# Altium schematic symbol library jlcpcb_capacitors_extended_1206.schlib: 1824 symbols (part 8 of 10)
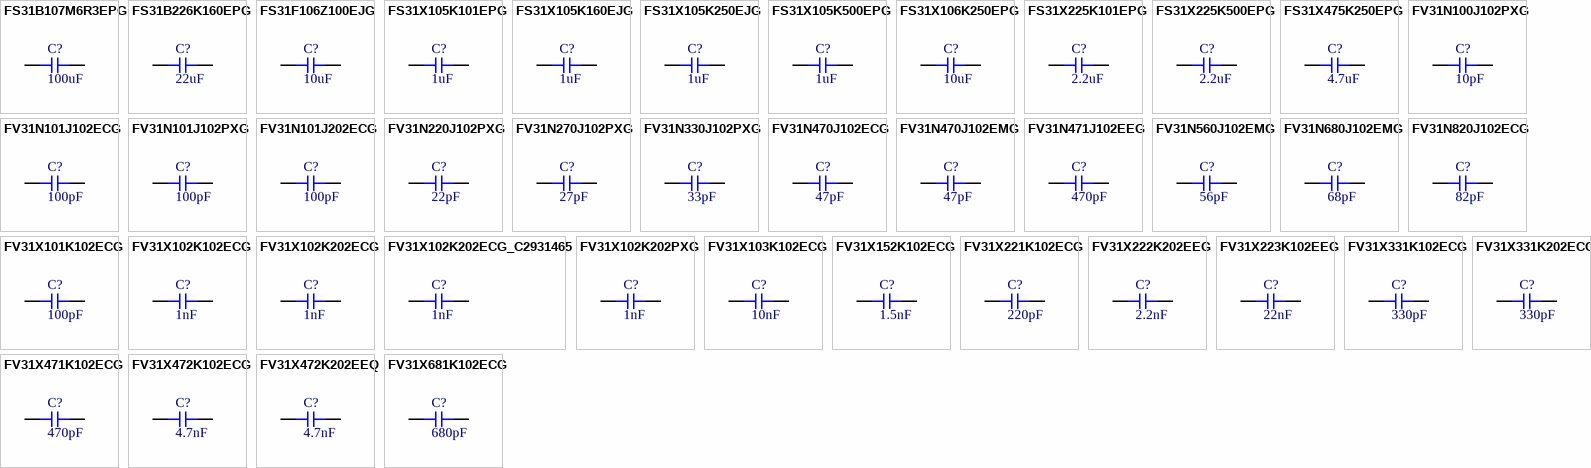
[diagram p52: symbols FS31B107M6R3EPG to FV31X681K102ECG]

## FV31X331K202ECG
designator C?  Capacitance: 330pF  (hidden comment: *)
Capacitor, Ceramic (MLCC), 330pF, ±10%, 2kV, X7R, ±10%, SMD 1206; Manufacturer: PSA(Prosperity Dielectrics); Manufacturer Part Number: FV31X331K202ECG
footprint CAP-1206 (1206 (3216M) Capacitor)
pins: 1, 2

## FV31X471K102ECG
designator C?  Capacitance: 470pF  (hidden comment: *)
Capacitor, Ceramic (MLCC), 470pF, ±10%, 1kV, X7R, ±10%, SMD 1206; Manufacturer: PSA(Prosperity Dielectrics); Manufacturer Part Number: FV31X471K102ECG
footprint CAP-1206 (1206 (3216M) Capacitor)
pins: 1, 2

## FV31X472K102ECG
designator C?  Capacitance: 4.7nF  (hidden comment: *)
Capacitor, Ceramic (MLCC), 4.7nF, ±10%, 1kV, X7R, ±10%, SMD 1206; Manufacturer: PSA(Prosperity Dielectrics); Manufacturer Part Number: FV31X472K102ECG
footprint CAP-1206 (1206 (3216M) Capacitor)
pins: 1, 2

## FV31X472K202EEQ
designator C?  Capacitance: 4.7nF  (hidden comment: *)
Capacitor, Ceramic (MLCC), 4.7nF, ±10%, 2kV, ±10%, SMD 1206; Manufacturer: PSA(Prosperity Dielectrics); Manufacturer Part Number: FV31X472K202EEQ
footprint CAP-1206 (1206 (3216M) Capacitor)
pins: 1, 2

## FV31X681K102ECG
designator C?  Capacitance: 680pF  (hidden comment: *)
Capacitor, Ceramic (MLCC), 680pF, ±10%, 1kV, X7R, ±10%, SMD 1206; Manufacturer: PSA(Prosperity Dielectrics); Manufacturer Part Number: FV31X681K102ECG
footprint CAP-1206 (1206 (3216M) Capacitor)
pins: 1, 2

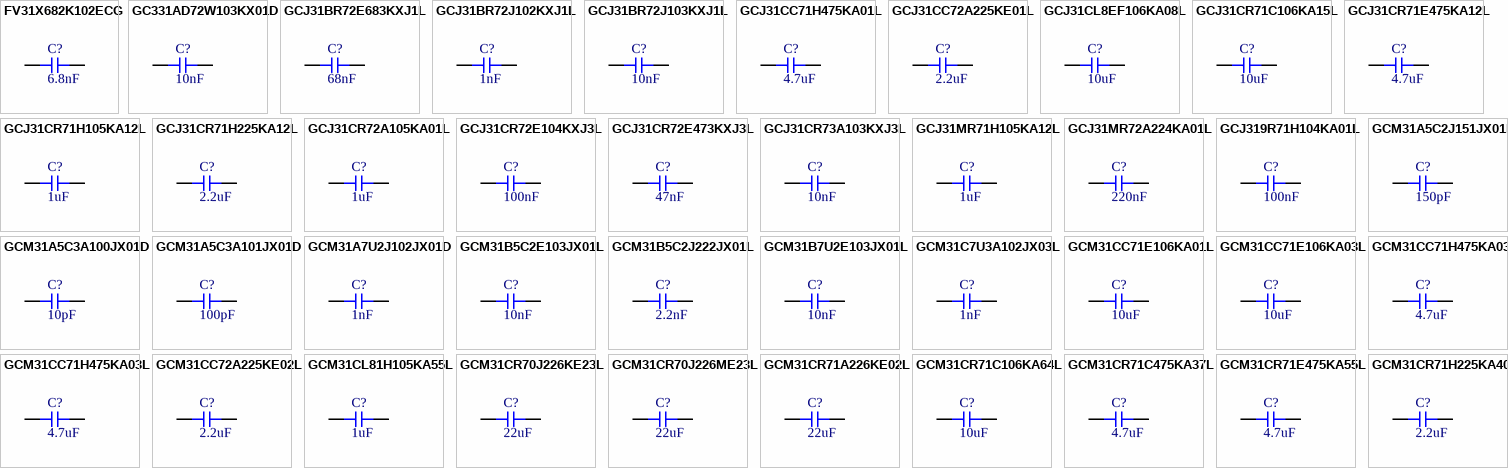
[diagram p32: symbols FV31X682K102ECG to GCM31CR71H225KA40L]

## FV31X682K102ECG
designator C?  Capacitance: 6.8nF  (hidden comment: *)
Capacitor, Ceramic (MLCC), 6.8nF, ±10%, 1kV, X7R, ±10%, SMD 1206; Manufacturer: PSA(Prosperity Dielectrics); Manufacturer Part Number: FV31X682K102ECG
footprint CAP-1206 (1206 (3216M) Capacitor)
pins: 1, 2

## GC331AD72W103KX01D
designator C?  Capacitance: 10nF  (hidden comment: *)
Capacitor, Ceramic (MLCC), 10nF, ±10%, 450V, X7T, ±10%, SMD 1206; Manufacturer: Murata Electronics; Manufacturer Part Number: GC331AD72W103KX01D
footprint CAP-1206 (1206 (3216M) Capacitor)
pins: 1, 2

## GCJ31BR72E683KXJ1L
designator C?  Capacitance: 68nF  (hidden comment: *)
Capacitor, Ceramic (MLCC), 68nF, ±10%, 250V, X7R, ±10%, SMD 1206; Manufacturer: Murata Electronics; Manufacturer Part Number: GCJ31BR72E683KXJ1L
footprint CAP-1206 (1206 (3216M) Capacitor)
pins: 1, 2

## GCJ31BR72J102KXJ1L
designator C?  Capacitance: 1nF  (hidden comment: *)
Capacitor, Ceramic (MLCC), 1nF, ±10%, 630V, X7R, ±10%, SMD 1206; Manufacturer: Murata Electronics; Manufacturer Part Number: GCJ31BR72J102KXJ1L
footprint CAP-1206 (1206 (3216M) Capacitor)
pins: 1, 2

## GCJ31BR72J103KXJ1L
designator C?  Capacitance: 10nF  (hidden comment: *)
Capacitor, Ceramic (MLCC), 10nF, ±10%, 630V, X7R, ±10%, SMD 1206; Manufacturer: Murata Electronics; Manufacturer Part Number: GCJ31BR72J103KXJ1L
footprint CAP-1206 (1206 (3216M) Capacitor)
pins: 1, 2

## GCJ31CC71H475KA01L
designator C?  Capacitance: 4.7uF  (hidden comment: *)
Capacitor, Ceramic (MLCC), 4.7uF, ±10%, 50V, X7S, ±10%, SMD 1206; Manufacturer: Murata Electronics; Manufacturer Part Number: GCJ31CC71H475KA01L
footprint CAP-1206 (1206 (3216M) Capacitor)
pins: 1, 2

## GCJ31CC72A225KE01L
designator C?  Capacitance: 2.2uF  (hidden comment: *)
Capacitor, Ceramic (MLCC), 2.2uF, ±10%, ±10%, SMD 1206; Manufacturer: Murata Electronics; Manufacturer Part Number: GCJ31CC72A225KE01L
footprint CAP-1206 (1206 (3216M) Capacitor)
pins: 1, 2

## GCJ31CL8EF106KA08L
designator C?  Capacitance: 10uF  (hidden comment: *)
Capacitor, Ceramic (MLCC), 10uF, ±10%, X8L, ±10%, SMD 1206; Manufacturer: Murata Electronics; Manufacturer Part Number: GCJ31CL8EF106KA08L
footprint CAP-1206 (1206 (3216M) Capacitor)
pins: 1, 2

## GCJ31CR71C106KA15L
designator C?  Capacitance: 10uF  (hidden comment: *)
Capacitor, Ceramic (MLCC), 10uF, ±10%, ±10%, SMD 1206; Manufacturer: Murata Electronics; Manufacturer Part Number: GCJ31CR71C106KA15L
footprint CAP-1206 (1206 (3216M) Capacitor)
pins: 1, 2

## GCJ31CR71E475KA12L
designator C?  Capacitance: 4.7uF  (hidden comment: *)
Capacitor, Ceramic (MLCC), 4.7uF, ±10%, 25V, X7R, ±10%, SMD 1206; Manufacturer: Murata Electronics; Manufacturer Part Number: GCJ31CR71E475KA12L
footprint CAP-1206 (1206 (3216M) Capacitor)
pins: 1, 2

## GCJ31CR71H105KA12L
designator C?  Capacitance: 1uF  (hidden comment: *)
Capacitor, Ceramic (MLCC), 1uF, ±10%, 50V, X7R, ±10%, SMD 1206; Manufacturer: Murata Electronics; Manufacturer Part Number: GCJ31CR71H105KA12L
footprint CAP-1206 (1206 (3216M) Capacitor)
pins: 1, 2

## GCJ31CR71H225KA12L
designator C?  Capacitance: 2.2uF  (hidden comment: *)
Capacitor, Ceramic (MLCC), 2.2uF, ±10%, 50V, X7R, ±10%, SMD 1206; Manufacturer: Murata Electronics; Manufacturer Part Number: GCJ31CR71H225KA12L
footprint CAP-1206 (1206 (3216M) Capacitor)
pins: 1, 2

## GCJ31CR72A105KA01L
designator C?  Capacitance: 1uF  (hidden comment: *)
Capacitor, Ceramic (MLCC), 1uF, ±10%, 100V, X7R, ±10%, SMD 1206; Manufacturer: Murata Electronics; Manufacturer Part Number: GCJ31CR72A105KA01L
footprint CAP-1206 (1206 (3216M) Capacitor)
pins: 1, 2

## GCJ31CR72E104KXJ3L
designator C?  Capacitance: 100nF  (hidden comment: *)
Capacitor, Ceramic (MLCC), 100nF, ±10%, 250V, X7R, ±10%, SMD 1206; Manufacturer: Murata Electronics; Manufacturer Part Number: GCJ31CR72E104KXJ3L
footprint CAP-1206 (1206 (3216M) Capacitor)
pins: 1, 2

## GCJ31CR72E473KXJ3L
designator C?  Capacitance: 47nF  (hidden comment: *)
Capacitor, Ceramic (MLCC), 47nF, ±10%, 250V, X7R, ±10%, SMD 1206; Manufacturer: Murata Electronics; Manufacturer Part Number: GCJ31CR72E473KXJ3L
footprint CAP-1206 (1206 (3216M) Capacitor)
pins: 1, 2

## GCJ31CR73A103KXJ3L
designator C?  Capacitance: 10nF  (hidden comment: *)
Capacitor, Ceramic (MLCC), 10nF, ±10%, 1kV, X7R, ±10%, SMD 1206; Manufacturer: Murata Electronics; Manufacturer Part Number: GCJ31CR73A103KXJ3L
footprint CAP-1206 (1206 (3216M) Capacitor)
pins: 1, 2

## GCJ31MR71H105KA12L
designator C?  Capacitance: 1uF  (hidden comment: *)
Capacitor, Ceramic (MLCC), 1uF, ±10%, 50V, X7R, ±10%, SMD 1206; Manufacturer: Murata Electronics; Manufacturer Part Number: GCJ31MR71H105KA12L
footprint CAP-1206 (1206 (3216M) Capacitor)
pins: 1, 2

## GCJ31MR72A224KA01L
designator C?  Capacitance: 220nF  (hidden comment: *)
Capacitor, Ceramic (MLCC), 220nF, ±10%, 100V, X7R, ±10%, SMD 1206; Manufacturer: Murata Electronics; Manufacturer Part Number: GCJ31MR72A224KA01L
footprint CAP-1206 (1206 (3216M) Capacitor)
pins: 1, 2

## GCJ319R71H104KA01L
designator C?  Capacitance: 100nF  (hidden comment: *)
Capacitor, Ceramic (MLCC), 100nF, ±10%, 50V, X7R, ±10%, SMD 1206; Manufacturer: Murata Electronics; Manufacturer Part Number: GCJ319R71H104KA01L
footprint CAP-1206 (1206 (3216M) Capacitor)
pins: 1, 2

## GCM31A5C2J151JX01D
designator C?  Capacitance: 150pF  (hidden comment: *)
Capacitor, Ceramic (MLCC), 150pF, ±5%, 630V, C0G, ±5%, SMD 1206; Manufacturer: Murata Electronics; Manufacturer Part Number: GCM31A5C2J151JX01D
footprint CAP-1206 (1206 (3216M) Capacitor)
pins: 1, 2

## GCM31A5C3A100JX01D
designator C?  Capacitance: 10pF  (hidden comment: *)
Capacitor, Ceramic (MLCC), 10pF, ±5%, 1kV, C0G, ±5%, SMD 1206; Manufacturer: Murata Electronics; Manufacturer Part Number: GCM31A5C3A100JX01D
footprint CAP-1206 (1206 (3216M) Capacitor)
pins: 1, 2

## GCM31A5C3A101JX01D
designator C?  Capacitance: 100pF  (hidden comment: *)
Capacitor, Ceramic (MLCC), 100pF, ±5%, 1kV, C0G, ±5%, SMD 1206; Manufacturer: Murata Electronics; Manufacturer Part Number: GCM31A5C3A101JX01D
footprint CAP-1206 (1206 (3216M) Capacitor)
pins: 1, 2

## GCM31A7U2J102JX01D
designator C?  Capacitance: 1nF  (hidden comment: *)
Capacitor, Ceramic (MLCC), 1nF, ±5%, 630V, U2J, ±5%, SMD 1206; Manufacturer: Murata Electronics; Manufacturer Part Number: GCM31A7U2J102JX01D
footprint CAP-1206 (1206 (3216M) Capacitor)
pins: 1, 2

## GCM31B5C2E103JX01L
designator C?  Capacitance: 10nF  (hidden comment: *)
Capacitor, Ceramic (MLCC), 10nF, ±5%, 250V, ±5%, SMD 1206; Manufacturer: Murata Electronics; Manufacturer Part Number: GCM31B5C2E103JX01L
footprint CAP-1206 (1206 (3216M) Capacitor)
pins: 1, 2

## GCM31B5C2J222JX01L
designator C?  Capacitance: 2.2nF  (hidden comment: *)
Capacitor, Ceramic (MLCC), 2.2nF, ±5%, ±5%, SMD 1206; Manufacturer: Murata Electronics; Manufacturer Part Number: GCM31B5C2J222JX01L
footprint CAP-1206 (1206 (3216M) Capacitor)
pins: 1, 2

## GCM31B7U2E103JX01L
designator C?  Capacitance: 10nF  (hidden comment: *)
Capacitor, Ceramic (MLCC), 10nF, ±5%, 250V, U2J, ±5%, SMD 1206; Manufacturer: Murata Electronics; Manufacturer Part Number: GCM31B7U2E103JX01L
footprint CAP-1206 (1206 (3216M) Capacitor)
pins: 1, 2

## GCM31C7U3A102JX03L
designator C?  Capacitance: 1nF  (hidden comment: *)
Capacitor, Ceramic (MLCC), 1nF, ±5%, 1kV, U2J, ±5%, SMD 1206; Manufacturer: Murata Electronics; Manufacturer Part Number: GCM31C7U3A102JX03L
footprint CAP-1206 (1206 (3216M) Capacitor)
pins: 1, 2

## GCM31CC71E106KA01L
designator C?  Capacitance: 10uF  (hidden comment: *)
Capacitor, Ceramic (MLCC), 10uF, ±10%, 25V, X7S, ±10%, SMD 1206; Manufacturer: Murata Electronics; Manufacturer Part Number: GCM31CC71E106KA01L
footprint CAP-1206 (1206 (3216M) Capacitor)
pins: 1, 2

## GCM31CC71E106KA03L
designator C?  Capacitance: 10uF  (hidden comment: *)
Capacitor, Ceramic (MLCC), 10uF, ±10%, 25V, X7S, ±10%, SMD 1206; Manufacturer: Murata Electronics; Manufacturer Part Number: GCM31CC71E106KA03L
footprint CAP-1206 (1206 (3216M) Capacitor)
pins: 1, 2

## GCM31CC71H475KA03K
designator C?  Capacitance: 4.7uF  (hidden comment: *)
Capacitor, Ceramic (MLCC), 4.7uF, ±10%, 50V, ±10%, SMD 1206; Manufacturer: Murata Electronics; Manufacturer Part Number: GCM31CC71H475KA03K
footprint CAP-1206 (1206 (3216M) Capacitor)
pins: 1, 2

## GCM31CC71H475KA03L
designator C?  Capacitance: 4.7uF  (hidden comment: *)
Capacitor, Ceramic (MLCC), 4.7uF, ±10%, 50V, X7S, ±10%, SMD 1206; Manufacturer: Murata Electronics; Manufacturer Part Number: GCM31CC71H475KA03L
footprint CAP-1206 (1206 (3216M) Capacitor)
pins: 1, 2

## GCM31CC72A225KE02L
designator C?  Capacitance: 2.2uF  (hidden comment: *)
Capacitor, Ceramic (MLCC), 2.2uF, ±10%, 100V, X7S, ±10%, SMD 1206; Manufacturer: Murata Electronics; Manufacturer Part Number: GCM31CC72A225KE02L
footprint CAP-1206 (1206 (3216M) Capacitor)
pins: 1, 2

## GCM31CL81H105KA55L
designator C?  Capacitance: 1uF  (hidden comment: *)
Capacitor, Ceramic (MLCC), 1uF, ±10%, 50V, X8L, ±10%, SMD 1206; Manufacturer: Murata Electronics; Manufacturer Part Number: GCM31CL81H105KA55L
footprint CAP-1206 (1206 (3216M) Capacitor)
pins: 1, 2

## GCM31CR70J226KE23L
designator C?  Capacitance: 22uF  (hidden comment: *)
Capacitor, Ceramic (MLCC), 22uF, ±10%, 6.3V, X7R, ±10%, SMD 1206; Manufacturer: Murata Electronics; Manufacturer Part Number: GCM31CR70J226KE23L
footprint CAP-1206 (1206 (3216M) Capacitor)
pins: 1, 2

## GCM31CR70J226ME23L
designator C?  Capacitance: 22uF  (hidden comment: *)
Capacitor, Ceramic (MLCC), 22uF, ±20%, 6.3V, X7R, ±20%, SMD 1206; Manufacturer: Murata Electronics; Manufacturer Part Number: GCM31CR70J226ME23L
footprint CAP-1206 (1206 (3216M) Capacitor)
pins: 1, 2

## GCM31CR71A226KE02L
designator C?  Capacitance: 22uF  (hidden comment: *)
Capacitor, Ceramic (MLCC), 22uF, ±10%, 10V, X7R, ±10%, SMD 1206; Manufacturer: Murata Electronics; Manufacturer Part Number: GCM31CR71A226KE02L
footprint CAP-1206 (1206 (3216M) Capacitor)
pins: 1, 2

## GCM31CR71C106KA64L
designator C?  Capacitance: 10uF  (hidden comment: *)
Capacitor, Ceramic (MLCC), 10uF, ±10%, 16V, X7R, ±10%, SMD 1206; Manufacturer: Murata Electronics; Manufacturer Part Number: GCM31CR71C106KA64L
footprint CAP-1206 (1206 (3216M) Capacitor)
pins: 1, 2

## GCM31CR71C475KA37L
designator C?  Capacitance: 4.7uF  (hidden comment: *)
Capacitor, Ceramic (MLCC), 4.7uF, ±10%, 16V, X7R, ±10%, SMD 1206; Manufacturer: Murata Electronics; Manufacturer Part Number: GCM31CR71C475KA37L
footprint CAP-1206 (1206 (3216M) Capacitor)
pins: 1, 2

## GCM31CR71E475KA55L
designator C?  Capacitance: 4.7uF  (hidden comment: *)
Capacitor, Ceramic (MLCC), 4.7uF, ±10%, 25V, X7R, ±10%, SMD 1206; Manufacturer: Murata Electronics; Manufacturer Part Number: GCM31CR71E475KA55L
footprint CAP-1206 (1206 (3216M) Capacitor)
pins: 1, 2

## GCM31CR71H225KA40L
designator C?  Capacitance: 2.2uF  (hidden comment: *)
Capacitor, Ceramic (MLCC), 2.2uF, ±10%, 50V, X7R, ±10%, SMD 1206; Manufacturer: Murata Electronics; Manufacturer Part Number: GCM31CR71H225KA40L
footprint CAP-1206 (1206 (3216M) Capacitor)
pins: 1, 2

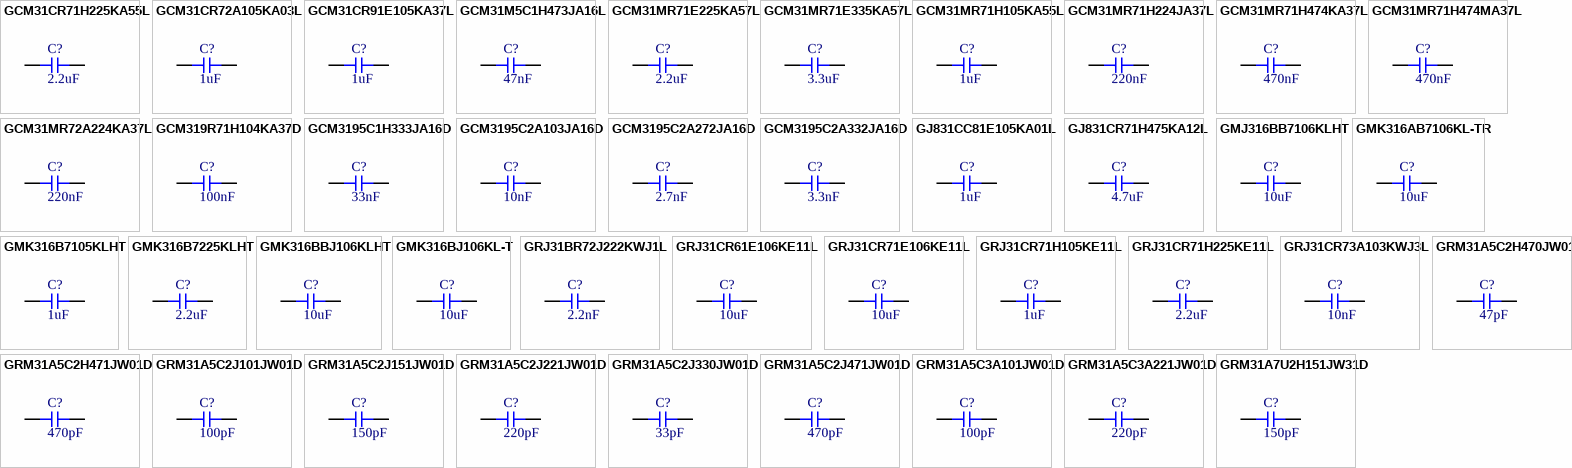
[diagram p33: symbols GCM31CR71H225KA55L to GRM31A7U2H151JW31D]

## GCM31CR71H225KA55L
designator C?  Capacitance: 2.2uF  (hidden comment: *)
Capacitor, Ceramic (MLCC), 2.2uF, ±10%, 50V, X7R, ±10%, SMD 1206; Manufacturer: Murata Electronics; Manufacturer Part Number: GCM31CR71H225KA55L
footprint CAP-1206 (1206 (3216M) Capacitor)
pins: 1, 2

## GCM31CR72A105KA03L
designator C?  Capacitance: 1uF  (hidden comment: *)
Capacitor, Ceramic (MLCC), 1uF, ±10%, 100V, X7R, ±10%, SMD 1206; Manufacturer: Murata Electronics; Manufacturer Part Number: GCM31CR72A105KA03L
footprint CAP-1206 (1206 (3216M) Capacitor)
pins: 1, 2

## GCM31CR91E105KA37L
designator C?  Capacitance: 1uF  (hidden comment: *)
Capacitor, Ceramic (MLCC), 1uF, ±10%, 25V, X8R, ±10%, SMD 1206; Manufacturer: Murata Electronics; Manufacturer Part Number: GCM31CR91E105KA37L
footprint CAP-1206 (1206 (3216M) Capacitor)
pins: 1, 2

## GCM31M5C1H473JA16L
designator C?  Capacitance: 47nF  (hidden comment: *)
Capacitor, Ceramic (MLCC), 47nF, ±5%, ±5%, SMD 1206; Manufacturer: Murata Electronics; Manufacturer Part Number: GCM31M5C1H473JA16L
footprint CAP-1206 (1206 (3216M) Capacitor)
pins: 1, 2

## GCM31MR71E225KA57L
designator C?  Capacitance: 2.2uF  (hidden comment: *)
Capacitor, Ceramic (MLCC), 2.2uF, ±10%, 25V, X7R, ±10%, SMD 1206; Manufacturer: Murata Electronics; Manufacturer Part Number: GCM31MR71E225KA57L
footprint CAP-1206 (1206 (3216M) Capacitor)
pins: 1, 2

## GCM31MR71E335KA57L
designator C?  Capacitance: 3.3uF  (hidden comment: *)
Capacitor, Ceramic (MLCC), 3.3uF, ±10%, 25V, X7R, ±10%, SMD 1206; Manufacturer: Murata Electronics; Manufacturer Part Number: GCM31MR71E335KA57L
footprint CAP-1206 (1206 (3216M) Capacitor)
pins: 1, 2

## GCM31MR71H105KA55L
designator C?  Capacitance: 1uF  (hidden comment: *)
Capacitor, Ceramic (MLCC), 1uF, ±10%, 50V, X7R, ±10%, SMD 1206; Manufacturer: Murata Electronics; Manufacturer Part Number: GCM31MR71H105KA55L
footprint CAP-1206 (1206 (3216M) Capacitor)
pins: 1, 2

## GCM31MR71H224JA37L
designator C?  Capacitance: 220nF  (hidden comment: *)
Capacitor, Ceramic (MLCC), 220nF, ±5%, 50V, X7R, ±5%, SMD 1206; Manufacturer: Murata Electronics; Manufacturer Part Number: GCM31MR71H224JA37L
footprint CAP-1206 (1206 (3216M) Capacitor)
pins: 1, 2

## GCM31MR71H474KA37L
designator C?  Capacitance: 470nF  (hidden comment: *)
Capacitor, Ceramic (MLCC), 470nF, ±10%, 50V, X7R, ±10%, SMD 1206; Manufacturer: Murata Electronics; Manufacturer Part Number: GCM31MR71H474KA37L
footprint CAP-1206 (1206 (3216M) Capacitor)
pins: 1, 2

## GCM31MR71H474MA37L
designator C?  Capacitance: 470nF  (hidden comment: *)
Capacitor, Ceramic (MLCC), 470nF, ±20%, 50V, X7R, ±20%, SMD 1206; Manufacturer: Murata Electronics; Manufacturer Part Number: GCM31MR71H474MA37L
footprint CAP-1206 (1206 (3216M) Capacitor)
pins: 1, 2

## GCM31MR72A224KA37L
designator C?  Capacitance: 220nF  (hidden comment: *)
Capacitor, Ceramic (MLCC), 220nF, ±10%, 100V, X7R, ±10%, SMD 1206; Manufacturer: Murata Electronics; Manufacturer Part Number: GCM31MR72A224KA37L
footprint CAP-1206 (1206 (3216M) Capacitor)
pins: 1, 2

## GCM319R71H104KA37D
designator C?  Capacitance: 100nF  (hidden comment: *)
Capacitor, Ceramic (MLCC), 100nF, ±10%, 50V, X7R, ±10%, SMD 1206; Manufacturer: Murata Electronics; Manufacturer Part Number: GCM319R71H104KA37D
footprint CAP-1206 (1206 (3216M) Capacitor)
pins: 1, 2

## GCM3195C1H333JA16D
designator C?  Capacitance: 33nF  (hidden comment: *)
Capacitor, Ceramic (MLCC), 33nF, ±5%, 50V, C0G, ±5%, SMD 1206; Manufacturer: Murata Electronics; Manufacturer Part Number: GCM3195C1H333JA16D
footprint CAP-1206 (1206 (3216M) Capacitor)
pins: 1, 2

## GCM3195C2A103JA16D
designator C?  Capacitance: 10nF  (hidden comment: *)
Capacitor, Ceramic (MLCC), 10nF, ±5%, 100V, C0G, ±5%, SMD 1206; Manufacturer: Murata Electronics; Manufacturer Part Number: GCM3195C2A103JA16D
footprint CAP-1206 (1206 (3216M) Capacitor)
pins: 1, 2

## GCM3195C2A272JA16D
designator C?  Capacitance: 2.7nF  (hidden comment: *)
Capacitor, Ceramic (MLCC), 2.7nF, ±5%, 100V, C0G, ±5%, SMD 1206; Manufacturer: Murata Electronics; Manufacturer Part Number: GCM3195C2A272JA16D
footprint CAP-1206 (1206 (3216M) Capacitor)
pins: 1, 2

## GCM3195C2A332JA16D
designator C?  Capacitance: 3.3nF  (hidden comment: *)
Capacitor, Ceramic (MLCC), 3.3nF, ±5%, 100V, C0G, ±5%, SMD 1206; Manufacturer: Murata Electronics; Manufacturer Part Number: GCM3195C2A332JA16D
footprint CAP-1206 (1206 (3216M) Capacitor)
pins: 1, 2

## GJ831CC81E105KA01L
designator C?  Capacitance: 1uF  (hidden comment: *)
Capacitor, Ceramic (MLCC), 1uF, ±10%, 25V, X6S, ±10%, SMD 1206; Manufacturer: Murata Electronics; Manufacturer Part Number: GJ831CC81E105KA01L
footprint CAP-1206 (1206 (3216M) Capacitor)
pins: 1, 2

## GJ831CR71H475KA12L
designator C?  Capacitance: 4.7uF  (hidden comment: *)
Capacitor, Ceramic (MLCC), 4.7uF, ±10%, 50V, X7R, ±10%, SMD 1206; Manufacturer: Murata Electronics; Manufacturer Part Number: GJ831CR71H475KA12L
footprint CAP-1206 (1206 (3216M) Capacitor)
pins: 1, 2

## GMJ316BB7106KLHT
designator C?  Capacitance: 10uF  (hidden comment: *)
Capacitor, Ceramic (MLCC), 10uF, ±10%, 35V, X7R, ±10%, SMD 1206; Manufacturer: Taiyo Yuden; Manufacturer Part Number: GMJ316BB7106KLHT
footprint CAP-1206 (1206 (3216M) Capacitor)
pins: 1, 2

## GMK316AB7106KL-TR
designator C?  Capacitance: 10uF  (hidden comment: *)
Capacitor, Ceramic (MLCC), 10uF, ±10%, 35V, X7R, ±10%, SMD 1206; Manufacturer: Taiyo Yuden; Manufacturer Part Number: GMK316AB7106KL-TR
footprint CAP-1206 (1206 (3216M) Capacitor)
pins: 1, 2

## GMK316B7105KLHT
designator C?  Capacitance: 1uF  (hidden comment: *)
Capacitor, Ceramic (MLCC), 1uF, ±10%, 35V, X7R, ±10%, SMD 1206; Manufacturer: Taiyo Yuden; Manufacturer Part Number: GMK316B7105KLHT
footprint CAP-1206 (1206 (3216M) Capacitor)
pins: 1, 2

## GMK316B7225KLHT
designator C?  Capacitance: 2.2uF  (hidden comment: *)
Capacitor, Ceramic (MLCC), 2.2uF, ±10%, 35V, X7R, ±10%, SMD 1206; Manufacturer: Taiyo Yuden; Manufacturer Part Number: GMK316B7225KLHT
footprint CAP-1206 (1206 (3216M) Capacitor)
pins: 1, 2

## GMK316BBJ106KLHT
designator C?  Capacitance: 10uF  (hidden comment: *)
Capacitor, Ceramic (MLCC), 10uF, ±10%, 35V, X5R, ±10%, SMD 1206; Manufacturer: Taiyo Yuden; Manufacturer Part Number: GMK316BBJ106KLHT
footprint CAP-1206 (1206 (3216M) Capacitor)
pins: 1, 2

## GMK316BJ106KL-T
designator C?  Capacitance: 10uF  (hidden comment: *)
Capacitor, Ceramic (MLCC), 10uF, ±10%, 35V, X5R, ±10%, SMD 1206; Manufacturer: Taiyo Yuden; Manufacturer Part Number: GMK316BJ106KL-T
footprint CAP-1206 (1206 (3216M) Capacitor)
pins: 1, 2

## GRJ31BR72J222KWJ1L
designator C?  Capacitance: 2.2nF  (hidden comment: *)
Capacitor, Ceramic (MLCC), 2.2nF, ±10%, 630V, X7R, ±10%, SMD 1206; Manufacturer: Murata Electronics; Manufacturer Part Number: GRJ31BR72J222KWJ1L
footprint CAP-1206 (1206 (3216M) Capacitor)
pins: 1, 2

## GRJ31CR61E106KE11L
designator C?  Capacitance: 10uF  (hidden comment: *)
Capacitor, Ceramic (MLCC), 10uF, ±10%, 25V, X5R, ±10%, SMD 1206; Manufacturer: Murata Electronics; Manufacturer Part Number: GRJ31CR61E106KE11L
footprint CAP-1206 (1206 (3216M) Capacitor)
pins: 1, 2

## GRJ31CR71E106KE11L
designator C?  Capacitance: 10uF  (hidden comment: *)
Capacitor, Ceramic (MLCC), 10uF, ±10%, 25V, X7R, ±10%, SMD 1206; Manufacturer: Murata Electronics; Manufacturer Part Number: GRJ31CR71E106KE11L
footprint CAP-1206 (1206 (3216M) Capacitor)
pins: 1, 2

## GRJ31CR71H105KE11L
designator C?  Capacitance: 1uF  (hidden comment: *)
Capacitor, Ceramic (MLCC), 1uF, ±10%, 50V, X7R, ±10%, SMD 1206; Manufacturer: Murata Electronics; Manufacturer Part Number: GRJ31CR71H105KE11L
footprint CAP-1206 (1206 (3216M) Capacitor)
pins: 1, 2

## GRJ31CR71H225KE11L
designator C?  Capacitance: 2.2uF  (hidden comment: *)
Capacitor, Ceramic (MLCC), 2.2uF, ±10%, 50V, X7R, ±10%, SMD 1206; Manufacturer: Murata Electronics; Manufacturer Part Number: GRJ31CR71H225KE11L
footprint CAP-1206 (1206 (3216M) Capacitor)
pins: 1, 2

## GRJ31CR73A103KWJ3L
designator C?  Capacitance: 10nF  (hidden comment: *)
Capacitor, Ceramic (MLCC), 10nF, ±10%, 1kV, X7R, ±10%, SMD 1206; Manufacturer: Murata Electronics; Manufacturer Part Number: GRJ31CR73A103KWJ3L
footprint CAP-1206 (1206 (3216M) Capacitor)
pins: 1, 2

## GRM31A5C2H470JW01D
designator C?  Capacitance: 47pF  (hidden comment: *)
Capacitor, Ceramic (MLCC), 47pF, ±5%, 500V, C0G, ±5%, SMD 1206; Manufacturer: Murata Electronics; Manufacturer Part Number: GRM31A5C2H470JW01D
footprint CAP-1206 (1206 (3216M) Capacitor)
pins: 1, 2

## GRM31A5C2H471JW01D
designator C?  Capacitance: 470pF  (hidden comment: *)
Capacitor, Ceramic (MLCC), 470pF, ±5%, 500V, C0G, ±5%, SMD 1206; Manufacturer: Murata Electronics; Manufacturer Part Number: GRM31A5C2H471JW01D
footprint CAP-1206 (1206 (3216M) Capacitor)
pins: 1, 2

## GRM31A5C2J101JW01D
designator C?  Capacitance: 100pF  (hidden comment: *)
Capacitor, Ceramic (MLCC), 100pF, ±5%, 630V, C0G, ±5%, SMD 1206; Manufacturer: Murata Electronics; Manufacturer Part Number: GRM31A5C2J101JW01D
footprint CAP-1206 (1206 (3216M) Capacitor)
pins: 1, 2

## GRM31A5C2J151JW01D
designator C?  Capacitance: 150pF  (hidden comment: *)
Capacitor, Ceramic (MLCC), 150pF, ±5%, 630V, C0G, ±5%, SMD 1206; Manufacturer: Murata Electronics; Manufacturer Part Number: GRM31A5C2J151JW01D
footprint CAP-1206 (1206 (3216M) Capacitor)
pins: 1, 2

## GRM31A5C2J221JW01D
designator C?  Capacitance: 220pF  (hidden comment: *)
Capacitor, Ceramic (MLCC), 220pF, ±5%, 630V, C0G, ±5%, SMD 1206; Manufacturer: Murata Electronics; Manufacturer Part Number: GRM31A5C2J221JW01D
footprint CAP-1206 (1206 (3216M) Capacitor)
pins: 1, 2

## GRM31A5C2J330JW01D
designator C?  Capacitance: 33pF  (hidden comment: *)
Capacitor, Ceramic (MLCC), 33pF, ±5%, 630V, C0G, ±5%, SMD 1206; Manufacturer: Murata Electronics; Manufacturer Part Number: GRM31A5C2J330JW01D
footprint CAP-1206 (1206 (3216M) Capacitor)
pins: 1, 2

## GRM31A5C2J471JW01D
designator C?  Capacitance: 470pF  (hidden comment: *)
Capacitor, Ceramic (MLCC), 470pF, ±5%, 630V, C0G, ±5%, SMD 1206; Manufacturer: Murata Electronics; Manufacturer Part Number: GRM31A5C2J471JW01D
footprint CAP-1206 (1206 (3216M) Capacitor)
pins: 1, 2

## GRM31A5C3A101JW01D
designator C?  Capacitance: 100pF  (hidden comment: *)
Capacitor, Ceramic (MLCC), 100pF, ±5%, 1kV, C0G, ±5%, SMD 1206; Manufacturer: Murata Electronics; Manufacturer Part Number: GRM31A5C3A101JW01D
footprint CAP-1206 (1206 (3216M) Capacitor)
pins: 1, 2

## GRM31A5C3A221JW01D
designator C?  Capacitance: 220pF  (hidden comment: *)
Capacitor, Ceramic (MLCC), 220pF, ±5%, 1kV, C0G, ±5%, SMD 1206; Manufacturer: Murata Electronics; Manufacturer Part Number: GRM31A5C3A221JW01D
footprint CAP-1206 (1206 (3216M) Capacitor)
pins: 1, 2

## GRM31A7U2H151JW31D
designator C?  Capacitance: 150pF  (hidden comment: *)
Capacitor, Ceramic (MLCC), 150pF, ±5%, 500V, U2J, ±5%, SMD 1206; Manufacturer: Murata Electronics; Manufacturer Part Number: GRM31A7U2H151JW31D
footprint CAP-1206 (1206 (3216M) Capacitor)
pins: 1, 2

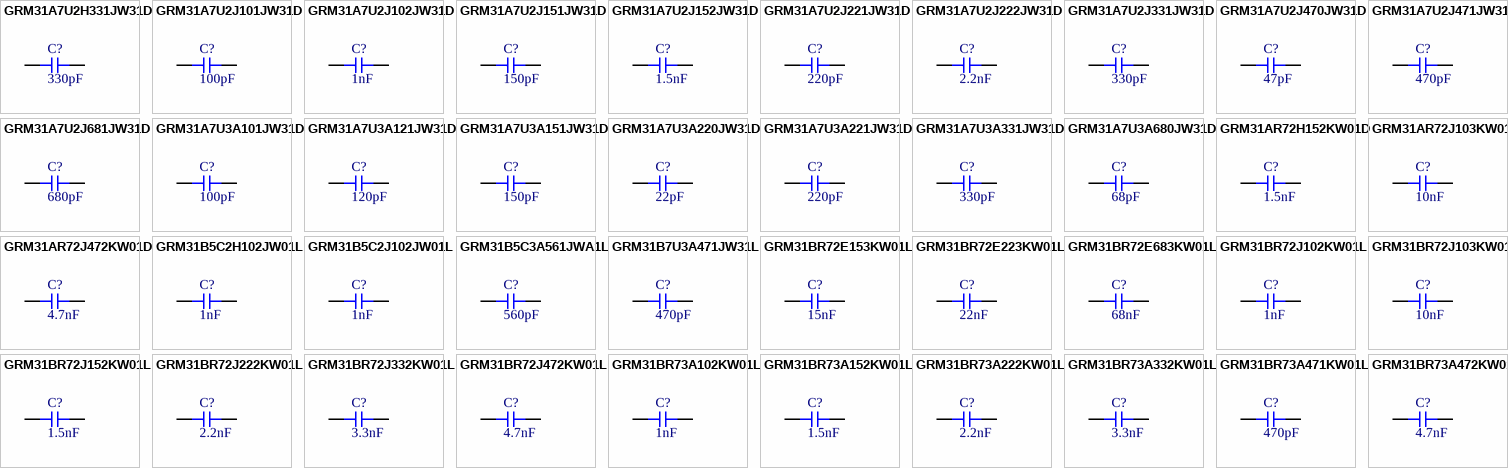
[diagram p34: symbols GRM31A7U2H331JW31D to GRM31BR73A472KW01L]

## GRM31A7U2H331JW31D
designator C?  Capacitance: 330pF  (hidden comment: *)
Capacitor, Ceramic (MLCC), 330pF, ±5%, 500V, U2J, ±5%, SMD 1206; Manufacturer: Murata Electronics; Manufacturer Part Number: GRM31A7U2H331JW31D
footprint CAP-1206 (1206 (3216M) Capacitor)
pins: 1, 2

## GRM31A7U2J101JW31D
designator C?  Capacitance: 100pF  (hidden comment: *)
Capacitor, Ceramic (MLCC), 100pF, ±5%, 630V, U2J, ±5%, SMD 1206; Manufacturer: Murata Electronics; Manufacturer Part Number: GRM31A7U2J101JW31D
footprint CAP-1206 (1206 (3216M) Capacitor)
pins: 1, 2

## GRM31A7U2J102JW31D
designator C?  Capacitance: 1nF  (hidden comment: *)
Capacitor, Ceramic (MLCC), 1nF, ±5%, 630V, U2J, ±5%, SMD 1206; Manufacturer: Murata Electronics; Manufacturer Part Number: GRM31A7U2J102JW31D
footprint CAP-1206 (1206 (3216M) Capacitor)
pins: 1, 2

## GRM31A7U2J151JW31D
designator C?  Capacitance: 150pF  (hidden comment: *)
Capacitor, Ceramic (MLCC), 150pF, ±5%, 630V, U2J, ±5%, SMD 1206; Manufacturer: Murata Electronics; Manufacturer Part Number: GRM31A7U2J151JW31D
footprint CAP-1206 (1206 (3216M) Capacitor)
pins: 1, 2

## GRM31A7U2J152JW31D
designator C?  Capacitance: 1.5nF  (hidden comment: *)
Capacitor, Ceramic (MLCC), 1.5nF, ±5%, 630V, U2J, ±5%, SMD 1206; Manufacturer: Murata Electronics; Manufacturer Part Number: GRM31A7U2J152JW31D
footprint CAP-1206 (1206 (3216M) Capacitor)
pins: 1, 2

## GRM31A7U2J221JW31D
designator C?  Capacitance: 220pF  (hidden comment: *)
Capacitor, Ceramic (MLCC), 220pF, ±5%, 630V, U2J, ±5%, SMD 1206; Manufacturer: Murata Electronics; Manufacturer Part Number: GRM31A7U2J221JW31D
footprint CAP-1206 (1206 (3216M) Capacitor)
pins: 1, 2

## GRM31A7U2J222JW31D
designator C?  Capacitance: 2.2nF  (hidden comment: *)
Capacitor, Ceramic (MLCC), 2.2nF, ±5%, 630V, U2J, ±5%, SMD 1206; Manufacturer: Murata Electronics; Manufacturer Part Number: GRM31A7U2J222JW31D
footprint CAP-1206 (1206 (3216M) Capacitor)
pins: 1, 2

## GRM31A7U2J331JW31D
designator C?  Capacitance: 330pF  (hidden comment: *)
Capacitor, Ceramic (MLCC), 330pF, ±5%, 630V, U2J, ±5%, SMD 1206; Manufacturer: Murata Electronics; Manufacturer Part Number: GRM31A7U2J331JW31D
footprint CAP-1206 (1206 (3216M) Capacitor)
pins: 1, 2

## GRM31A7U2J470JW31D
designator C?  Capacitance: 47pF  (hidden comment: *)
Capacitor, Ceramic (MLCC), 47pF, ±5%, 630V, U2J, ±5%, SMD 1206; Manufacturer: Murata Electronics; Manufacturer Part Number: GRM31A7U2J470JW31D
footprint CAP-1206 (1206 (3216M) Capacitor)
pins: 1, 2

## GRM31A7U2J471JW31D
designator C?  Capacitance: 470pF  (hidden comment: *)
Capacitor, Ceramic (MLCC), 470pF, ±5%, 630V, U2J, ±5%, SMD 1206; Manufacturer: Murata Electronics; Manufacturer Part Number: GRM31A7U2J471JW31D
footprint CAP-1206 (1206 (3216M) Capacitor)
pins: 1, 2

## GRM31A7U2J681JW31D
designator C?  Capacitance: 680pF  (hidden comment: *)
Capacitor, Ceramic (MLCC), 680pF, ±5%, 630V, U2J, ±5%, SMD 1206; Manufacturer: Murata Electronics; Manufacturer Part Number: GRM31A7U2J681JW31D
footprint CAP-1206 (1206 (3216M) Capacitor)
pins: 1, 2

## GRM31A7U3A101JW31D
designator C?  Capacitance: 100pF  (hidden comment: *)
Capacitor, Ceramic (MLCC), 100pF, ±5%, 1kV, U2J, ±5%, SMD 1206; Manufacturer: Murata Electronics; Manufacturer Part Number: GRM31A7U3A101JW31D
footprint CAP-1206 (1206 (3216M) Capacitor)
pins: 1, 2

## GRM31A7U3A121JW31D
designator C?  Capacitance: 120pF  (hidden comment: *)
Capacitor, Ceramic (MLCC), 120pF, ±5%, 1kV, U2J, ±5%, SMD 1206; Manufacturer: Murata Electronics; Manufacturer Part Number: GRM31A7U3A121JW31D
footprint CAP-1206 (1206 (3216M) Capacitor)
pins: 1, 2

## GRM31A7U3A151JW31D
designator C?  Capacitance: 150pF  (hidden comment: *)
Capacitor, Ceramic (MLCC), 150pF, ±5%, 1kV, U2J, ±5%, SMD 1206; Manufacturer: Murata Electronics; Manufacturer Part Number: GRM31A7U3A151JW31D
footprint CAP-1206 (1206 (3216M) Capacitor)
pins: 1, 2

## GRM31A7U3A220JW31D
designator C?  Capacitance: 22pF  (hidden comment: *)
Capacitor, Ceramic (MLCC), 22pF, ±5%, 1kV, U2J, ±5%, SMD 1206; Manufacturer: Murata Electronics; Manufacturer Part Number: GRM31A7U3A220JW31D
footprint CAP-1206 (1206 (3216M) Capacitor)
pins: 1, 2

## GRM31A7U3A221JW31D
designator C?  Capacitance: 220pF  (hidden comment: *)
Capacitor, Ceramic (MLCC), 220pF, ±5%, 1kV, ±5%, SMD 1206; Manufacturer: Murata Electronics; Manufacturer Part Number: GRM31A7U3A221JW31D
footprint CAP-1206 (1206 (3216M) Capacitor)
pins: 1, 2

## GRM31A7U3A331JW31D
designator C?  Capacitance: 330pF  (hidden comment: *)
Capacitor, Ceramic (MLCC), 330pF, ±5%, 1kV, U2J, ±5%, SMD 1206; Manufacturer: Murata Electronics; Manufacturer Part Number: GRM31A7U3A331JW31D
footprint CAP-1206 (1206 (3216M) Capacitor)
pins: 1, 2

## GRM31A7U3A680JW31D
designator C?  Capacitance: 68pF  (hidden comment: *)
Capacitor, Ceramic (MLCC), 68pF, ±5%, 1kV, U2J, ±5%, SMD 1206; Manufacturer: Murata Electronics; Manufacturer Part Number: GRM31A7U3A680JW31D
footprint CAP-1206 (1206 (3216M) Capacitor)
pins: 1, 2

## GRM31AR72H152KW01D
designator C?  Capacitance: 1.5nF  (hidden comment: *)
Capacitor, Ceramic (MLCC), 1.5nF, ±10%, 500V, X7R, ±10%, SMD 1206; Manufacturer: Murata Electronics; Manufacturer Part Number: GRM31AR72H152KW01D
footprint CAP-1206 (1206 (3216M) Capacitor)
pins: 1, 2

## GRM31AR72J103KW01D
designator C?  Capacitance: 10nF  (hidden comment: *)
Capacitor, Ceramic (MLCC), 10nF, ±10%, 630V, X7R, ±10%, SMD 1206; Manufacturer: Murata Electronics; Manufacturer Part Number: GRM31AR72J103KW01D
footprint CAP-1206 (1206 (3216M) Capacitor)
pins: 1, 2

## GRM31AR72J472KW01D
designator C?  Capacitance: 4.7nF  (hidden comment: *)
Capacitor, Ceramic (MLCC), 4.7nF, ±10%, 630V, X7R, ±10%, SMD 1206; Manufacturer: Murata Electronics; Manufacturer Part Number: GRM31AR72J472KW01D
footprint CAP-1206 (1206 (3216M) Capacitor)
pins: 1, 2

## GRM31B5C2H102JW01L
designator C?  Capacitance: 1nF  (hidden comment: *)
Capacitor, Ceramic (MLCC), 1nF, ±5%, 500V, C0G, ±5%, SMD 1206; Manufacturer: Murata Electronics; Manufacturer Part Number: GRM31B5C2H102JW01L
footprint CAP-1206 (1206 (3216M) Capacitor)
pins: 1, 2

## GRM31B5C2J102JW01L
designator C?  Capacitance: 1nF  (hidden comment: *)
Capacitor, Ceramic (MLCC), 1nF, ±5%, 630V, C0G, ±5%, SMD 1206; Manufacturer: Murata Electronics; Manufacturer Part Number: GRM31B5C2J102JW01L
footprint CAP-1206 (1206 (3216M) Capacitor)
pins: 1, 2

## GRM31B5C3A561JWA1L
designator C?  Capacitance: 560pF  (hidden comment: *)
Capacitor, Ceramic (MLCC), 560pF, ±5%, 1kV, C0G, ±5%, SMD 1206; Manufacturer: Murata Electronics; Manufacturer Part Number: GRM31B5C3A561JWA1L
footprint CAP-1206 (1206 (3216M) Capacitor)
pins: 1, 2

## GRM31B7U3A471JW31L
designator C?  Capacitance: 470pF  (hidden comment: *)
Capacitor, Ceramic (MLCC), 470pF, ±5%, 1kV, U2J, ±5%, SMD 1206; Manufacturer: Murata Electronics; Manufacturer Part Number: GRM31B7U3A471JW31L
footprint CAP-1206 (1206 (3216M) Capacitor)
pins: 1, 2

## GRM31BR72E153KW01L
designator C?  Capacitance: 15nF  (hidden comment: *)
Capacitor, Ceramic (MLCC), 15nF, ±10%, 250V, X7R, ±10%, SMD 1206; Manufacturer: Murata Electronics; Manufacturer Part Number: GRM31BR72E153KW01L
footprint CAP-1206 (1206 (3216M) Capacitor)
pins: 1, 2

## GRM31BR72E223KW01L
designator C?  Capacitance: 22nF  (hidden comment: *)
Capacitor, Ceramic (MLCC), 22nF, ±10%, 250V, X7R, ±10%, SMD 1206; Manufacturer: Murata Electronics; Manufacturer Part Number: GRM31BR72E223KW01L
footprint CAP-1206 (1206 (3216M) Capacitor)
pins: 1, 2

## GRM31BR72E683KW01L
designator C?  Capacitance: 68nF  (hidden comment: *)
Capacitor, Ceramic (MLCC), 68nF, ±10%, 250V, X7R, ±10%, SMD 1206; Manufacturer: Murata Electronics; Manufacturer Part Number: GRM31BR72E683KW01L
footprint CAP-1206 (1206 (3216M) Capacitor)
pins: 1, 2

## GRM31BR72J102KW01L
designator C?  Capacitance: 1nF  (hidden comment: *)
Capacitor, Ceramic (MLCC), 1nF, ±10%, 630V, X7R, ±10%, SMD 1206; Manufacturer: Murata Electronics; Manufacturer Part Number: GRM31BR72J102KW01L
footprint CAP-1206 (1206 (3216M) Capacitor)
pins: 1, 2

## GRM31BR72J103KW01L
designator C?  Capacitance: 10nF  (hidden comment: *)
Capacitor, Ceramic (MLCC), 10nF, ±10%, 630V, X7R, ±10%, SMD 1206; Manufacturer: Murata Electronics; Manufacturer Part Number: GRM31BR72J103KW01L
footprint CAP-1206 (1206 (3216M) Capacitor)
pins: 1, 2

## GRM31BR72J152KW01L
designator C?  Capacitance: 1.5nF  (hidden comment: *)
Capacitor, Ceramic (MLCC), 1.5nF, ±10%, 630V, X7R, ±10%, SMD 1206; Manufacturer: Murata Electronics; Manufacturer Part Number: GRM31BR72J152KW01L
footprint CAP-1206 (1206 (3216M) Capacitor)
pins: 1, 2

## GRM31BR72J222KW01L
designator C?  Capacitance: 2.2nF  (hidden comment: *)
Capacitor, Ceramic (MLCC), 2.2nF, ±10%, 630V, X7R, ±10%, SMD 1206; Manufacturer: Murata Electronics; Manufacturer Part Number: GRM31BR72J222KW01L
footprint CAP-1206 (1206 (3216M) Capacitor)
pins: 1, 2

## GRM31BR72J332KW01L
designator C?  Capacitance: 3.3nF  (hidden comment: *)
Capacitor, Ceramic (MLCC), 3.3nF, ±10%, 630V, X7R, ±10%, SMD 1206; Manufacturer: Murata Electronics; Manufacturer Part Number: GRM31BR72J332KW01L
footprint CAP-1206 (1206 (3216M) Capacitor)
pins: 1, 2

## GRM31BR72J472KW01L
designator C?  Capacitance: 4.7nF  (hidden comment: *)
Capacitor, Ceramic (MLCC), 4.7nF, ±10%, 630V, X7R, ±10%, SMD 1206; Manufacturer: Murata Electronics; Manufacturer Part Number: GRM31BR72J472KW01L
footprint CAP-1206 (1206 (3216M) Capacitor)
pins: 1, 2

## GRM31BR73A102KW01L
designator C?  Capacitance: 1nF  (hidden comment: *)
Capacitor, Ceramic (MLCC), 1nF, ±10%, 1kV, X7R, ±10%, SMD 1206; Manufacturer: Murata Electronics; Manufacturer Part Number: GRM31BR73A102KW01L
footprint CAP-1206 (1206 (3216M) Capacitor)
pins: 1, 2

## GRM31BR73A152KW01L
designator C?  Capacitance: 1.5nF  (hidden comment: *)
Capacitor, Ceramic (MLCC), 1.5nF, ±10%, 1kV, X7R, ±10%, SMD 1206; Manufacturer: Murata Electronics; Manufacturer Part Number: GRM31BR73A152KW01L
footprint CAP-1206 (1206 (3216M) Capacitor)
pins: 1, 2

## GRM31BR73A222KW01L
designator C?  Capacitance: 2.2nF  (hidden comment: *)
Capacitor, Ceramic (MLCC), 2.2nF, ±10%, 1kV, X7R, ±10%, SMD 1206; Manufacturer: Murata Electronics; Manufacturer Part Number: GRM31BR73A222KW01L
footprint CAP-1206 (1206 (3216M) Capacitor)
pins: 1, 2

## GRM31BR73A332KW01L
designator C?  Capacitance: 3.3nF  (hidden comment: *)
Capacitor, Ceramic (MLCC), 3.3nF, ±10%, 1kV, X7R, ±10%, SMD 1206; Manufacturer: Murata Electronics; Manufacturer Part Number: GRM31BR73A332KW01L
footprint CAP-1206 (1206 (3216M) Capacitor)
pins: 1, 2

## GRM31BR73A471KW01L
designator C?  Capacitance: 470pF  (hidden comment: *)
Capacitor, Ceramic (MLCC), 470pF, ±10%, 1kV, X7R, ±10%, SMD 1206; Manufacturer: Murata Electronics; Manufacturer Part Number: GRM31BR73A471KW01L
footprint CAP-1206 (1206 (3216M) Capacitor)
pins: 1, 2

## GRM31BR73A472KW01L
designator C?  Capacitance: 4.7nF  (hidden comment: *)
Capacitor, Ceramic (MLCC), 4.7nF, ±10%, 1kV, X7R, ±10%, SMD 1206; Manufacturer: Murata Electronics; Manufacturer Part Number: GRM31BR73A472KW01L
footprint CAP-1206 (1206 (3216M) Capacitor)
pins: 1, 2

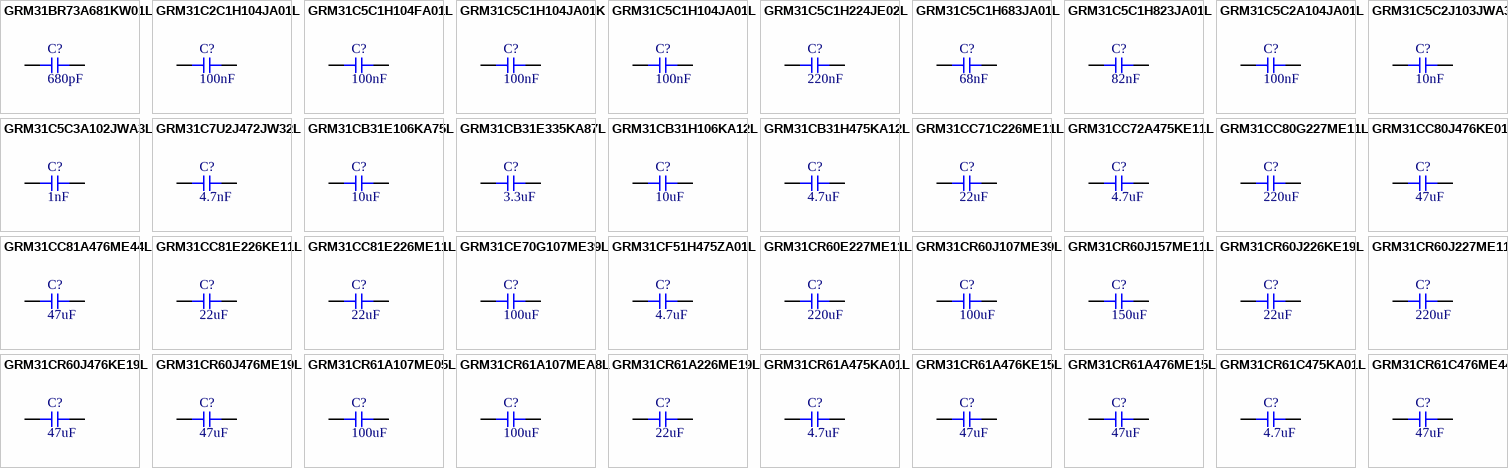
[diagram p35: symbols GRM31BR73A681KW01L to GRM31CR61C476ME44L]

## GRM31BR73A681KW01L
designator C?  Capacitance: 680pF  (hidden comment: *)
Capacitor, Ceramic (MLCC), 680pF, ±10%, 1kV, X7R, ±10%, SMD 1206; Manufacturer: Murata Electronics; Manufacturer Part Number: GRM31BR73A681KW01L
footprint CAP-1206 (1206 (3216M) Capacitor)
pins: 1, 2

## GRM31C2C1H104JA01L
designator C?  Capacitance: 100nF  (hidden comment: *)
Capacitor, Ceramic (MLCC), 100nF, ±5%, 50V, CH, ±5%, SMD 1206; Manufacturer: Murata Electronics; Manufacturer Part Number: GRM31C2C1H104JA01L
footprint CAP-1206 (1206 (3216M) Capacitor)
pins: 1, 2

## GRM31C5C1H104FA01L
designator C?  Capacitance: 100nF  (hidden comment: *)
Capacitor, Ceramic (MLCC), 100nF, ±1%, 50V, C0G, ±1%, SMD 1206; Manufacturer: Murata Electronics; Manufacturer Part Number: GRM31C5C1H104FA01L
footprint CAP-1206 (1206 (3216M) Capacitor)
pins: 1, 2

## GRM31C5C1H104JA01K
designator C?  Capacitance: 100nF  (hidden comment: *)
Capacitor, Ceramic (MLCC), 100nF, ±5%, 50V, C0G, ±5%, SMD 1206; Manufacturer: Murata Electronics; Manufacturer Part Number: GRM31C5C1H104JA01K
footprint CAP-1206 (1206 (3216M) Capacitor)
pins: 1, 2

## GRM31C5C1H104JA01L
designator C?  Capacitance: 100nF  (hidden comment: *)
Capacitor, Ceramic (MLCC), 100nF, ±5%, 50V, C0G, ±5%, SMD 1206; Manufacturer: Murata Electronics; Manufacturer Part Number: GRM31C5C1H104JA01L
footprint CAP-1206 (1206 (3216M) Capacitor)
pins: 1, 2

## GRM31C5C1H224JE02L
designator C?  Capacitance: 220nF  (hidden comment: *)
Capacitor, Ceramic (MLCC), 220nF, ±5%, 50V, C0G, ±5%, SMD 1206; Manufacturer: Murata Electronics; Manufacturer Part Number: GRM31C5C1H224JE02L
footprint CAP-1206 (1206 (3216M) Capacitor)
pins: 1, 2

## GRM31C5C1H683JA01L
designator C?  Capacitance: 68nF  (hidden comment: *)
Capacitor, Ceramic (MLCC), 68nF, ±5%, 50V, C0G, ±5%, SMD 1206; Manufacturer: Murata Electronics; Manufacturer Part Number: GRM31C5C1H683JA01L
footprint CAP-1206 (1206 (3216M) Capacitor)
pins: 1, 2

## GRM31C5C1H823JA01L
designator C?  Capacitance: 82nF  (hidden comment: *)
Capacitor, Ceramic (MLCC), 82nF, ±5%, 50V, C0G, ±5%, SMD 1206; Manufacturer: Murata Electronics; Manufacturer Part Number: GRM31C5C1H823JA01L
footprint CAP-1206 (1206 (3216M) Capacitor)
pins: 1, 2

## GRM31C5C2A104JA01L
designator C?  Capacitance: 100nF  (hidden comment: *)
Capacitor, Ceramic (MLCC), 100nF, ±5%, 100V, C0G, ±5%, SMD 1206; Manufacturer: Murata Electronics; Manufacturer Part Number: GRM31C5C2A104JA01L
footprint CAP-1206 (1206 (3216M) Capacitor)
pins: 1, 2

## GRM31C5C2J103JWA3L
designator C?  Capacitance: 10nF  (hidden comment: *)
Capacitor, Ceramic (MLCC), 10nF, ±5%, ±5%, SMD 1206; Manufacturer: Murata Electronics; Manufacturer Part Number: GRM31C5C2J103JWA3L
footprint CAP-1206 (1206 (3216M) Capacitor)
pins: 1, 2

## GRM31C5C3A102JWA3L
designator C?  Capacitance: 1nF  (hidden comment: *)
Capacitor, Ceramic (MLCC), 1nF, ±5%, 1kV, C0G, ±5%, SMD 1206; Manufacturer: Murata Electronics; Manufacturer Part Number: GRM31C5C3A102JWA3L
footprint CAP-1206 (1206 (3216M) Capacitor)
pins: 1, 2

## GRM31C7U2J472JW32L
designator C?  Capacitance: 4.7nF  (hidden comment: *)
Capacitor, Ceramic (MLCC), 4.7nF, ±5%, 630V, U2J, ±5%, SMD 1206; Manufacturer: Murata Electronics; Manufacturer Part Number: GRM31C7U2J472JW32L
footprint CAP-1206 (1206 (3216M) Capacitor)
pins: 1, 2

## GRM31CB31E106KA75L
designator C?  Capacitance: 10uF  (hidden comment: *)
Capacitor, Ceramic (MLCC), 10uF, ±10%, 25V, B, ±10%, SMD 1206; Manufacturer: Murata Electronics; Manufacturer Part Number: GRM31CB31E106KA75L
footprint CAP-1206 (1206 (3216M) Capacitor)
pins: 1, 2

## GRM31CB31E335KA87L
designator C?  Capacitance: 3.3uF  (hidden comment: *)
Capacitor, Ceramic (MLCC), 3.3uF, ±10%, 25V, B, ±10%, SMD 1206; Manufacturer: Murata Electronics; Manufacturer Part Number: GRM31CB31E335KA87L
footprint CAP-1206 (1206 (3216M) Capacitor)
pins: 1, 2

## GRM31CB31H106KA12L
designator C?  Capacitance: 10uF  (hidden comment: *)
Capacitor, Ceramic (MLCC), 10uF, ±10%, 50V, B, ±10%, SMD 1206; Manufacturer: Murata Electronics; Manufacturer Part Number: GRM31CB31H106KA12L
footprint CAP-1206 (1206 (3216M) Capacitor)
pins: 1, 2

## GRM31CB31H475KA12L
designator C?  Capacitance: 4.7uF  (hidden comment: *)
Capacitor, Ceramic (MLCC), 4.7uF, ±10%, 50V, B, ±10%, SMD 1206; Manufacturer: Murata Electronics; Manufacturer Part Number: GRM31CB31H475KA12L
footprint CAP-1206 (1206 (3216M) Capacitor)
pins: 1, 2

## GRM31CC71C226ME11L
designator C?  Capacitance: 22uF  (hidden comment: *)
Capacitor, Ceramic (MLCC), 22uF, ±20%, 16V, X7S, ±20%, SMD 1206; Manufacturer: Murata Electronics; Manufacturer Part Number: GRM31CC71C226ME11L
footprint CAP-1206 (1206 (3216M) Capacitor)
pins: 1, 2

## GRM31CC72A475KE11L
designator C?  Capacitance: 4.7uF  (hidden comment: *)
Capacitor, Ceramic (MLCC), 4.7uF, ±10%, 100V, X7S, ±10%, SMD 1206; Manufacturer: Murata Electronics; Manufacturer Part Number: GRM31CC72A475KE11L
footprint CAP-1206 (1206 (3216M) Capacitor)
pins: 1, 2

## GRM31CC80G227ME11L
designator C?  Capacitance: 220uF  (hidden comment: *)
Capacitor, Ceramic (MLCC), 220uF, ±20%, ±20%, SMD 1206; Manufacturer: Murata Electronics; Manufacturer Part Number: GRM31CC80G227ME11L
footprint CAP-1206 (1206 (3216M) Capacitor)
pins: 1, 2

## GRM31CC80J476KE01L
designator C?  Capacitance: 47uF  (hidden comment: *)
Capacitor, Ceramic (MLCC), 47uF, ±10%, ±10%, SMD 1206; Manufacturer: Murata Electronics; Manufacturer Part Number: GRM31CC80J476KE01L
footprint CAP-1206 (1206 (3216M) Capacitor)
pins: 1, 2

## GRM31CC81A476ME44L
designator C?  Capacitance: 47uF  (hidden comment: *)
Capacitor, Ceramic (MLCC), 47uF, ±20%, 10V, X6S, ±20%, SMD 1206; Manufacturer: Murata Electronics; Manufacturer Part Number: GRM31CC81A476ME44L
footprint CAP-1206 (1206 (3216M) Capacitor)
pins: 1, 2

## GRM31CC81E226KE11L
designator C?  Capacitance: 22uF  (hidden comment: *)
Capacitor, Ceramic (MLCC), 22uF, ±10%, 25V, X6S, ±10%, SMD 1206; Manufacturer: Murata Electronics; Manufacturer Part Number: GRM31CC81E226KE11L
footprint CAP-1206 (1206 (3216M) Capacitor)
pins: 1, 2

## GRM31CC81E226ME11L
designator C?  Capacitance: 22uF  (hidden comment: *)
Capacitor, Ceramic (MLCC), 22uF, ±20%, 25V, X6S, ±20%, SMD 1206; Manufacturer: Murata Electronics; Manufacturer Part Number: GRM31CC81E226ME11L
footprint CAP-1206 (1206 (3216M) Capacitor)
pins: 1, 2

## GRM31CE70G107ME39L
designator C?  Capacitance: 100uF  (hidden comment: *)
Capacitor, Ceramic (MLCC), 100uF, ±20%, 4V, X7U, ±20%, SMD 1206; Manufacturer: Murata Electronics; Manufacturer Part Number: GRM31CE70G107ME39L
footprint CAP-1206 (1206 (3216M) Capacitor)
pins: 1, 2

## GRM31CF51H475ZA01L
designator C?  Capacitance: 4.7uF  (hidden comment: *)
Capacitor, Ceramic (MLCC), 4.7uF, 50V, Y5V, SMD 1206; Manufacturer: Murata Electronics; Manufacturer Part Number: GRM31CF51H475ZA01L; Temperature Rating: -20%~+80%
footprint CAP-1206 (1206 (3216M) Capacitor)
pins: 1, 2

## GRM31CR60E227ME11L
designator C?  Capacitance: 220uF  (hidden comment: *)
Capacitor, Ceramic (MLCC), 220uF, ±20%, ±20%, SMD 1206; Manufacturer: Murata Electronics; Manufacturer Part Number: GRM31CR60E227ME11L
footprint CAP-1206 (1206 (3216M) Capacitor)
pins: 1, 2

## GRM31CR60J107ME39L
designator C?  Capacitance: 100uF  (hidden comment: *)
Capacitor, Ceramic (MLCC), 100uF, ±20%, 6.3V, X5R, ±20%, SMD 1206; Manufacturer: Murata Electronics; Manufacturer Part Number: GRM31CR60J107ME39L
footprint CAP-1206 (1206 (3216M) Capacitor)
pins: 1, 2

## GRM31CR60J157ME11L
designator C?  Capacitance: 150uF  (hidden comment: *)
Capacitor, Ceramic (MLCC), 150uF, ±20%, 6.3V, X5R, ±20%, SMD 1206; Manufacturer: Murata Electronics; Manufacturer Part Number: GRM31CR60J157ME11L
footprint CAP-1206 (1206 (3216M) Capacitor)
pins: 1, 2

## GRM31CR60J226KE19L
designator C?  Capacitance: 22uF  (hidden comment: *)
Capacitor, Ceramic (MLCC), 22uF, ±10%, 6.3V, X5R, ±10%, SMD 1206; Manufacturer: Murata Electronics; Manufacturer Part Number: GRM31CR60J226KE19L
footprint CAP-1206 (1206 (3216M) Capacitor)
pins: 1, 2

## GRM31CR60J227ME11L
designator C?  Capacitance: 220uF  (hidden comment: *)
Capacitor, Ceramic (MLCC), 220uF, ±20%, 6.3V, X5R, ±20%, SMD 1206; Manufacturer: Murata Electronics; Manufacturer Part Number: GRM31CR60J227ME11L
footprint CAP-1206 (1206 (3216M) Capacitor)
pins: 1, 2

## GRM31CR60J476KE19L
designator C?  Capacitance: 47uF  (hidden comment: *)
Capacitor, Ceramic (MLCC), 47uF, ±10%, 6.3V, X5R, ±10%, SMD 1206; Manufacturer: Murata Electronics; Manufacturer Part Number: GRM31CR60J476KE19L
footprint CAP-1206 (1206 (3216M) Capacitor)
pins: 1, 2

## GRM31CR60J476ME19L
designator C?  Capacitance: 47uF  (hidden comment: *)
Capacitor, Ceramic (MLCC), 47uF, ±20%, 6.3V, X5R, ±20%, SMD 1206; Manufacturer: Murata Electronics; Manufacturer Part Number: GRM31CR60J476ME19L
footprint CAP-1206 (1206 (3216M) Capacitor)
pins: 1, 2

## GRM31CR61A107ME05L
designator C?  Capacitance: 100uF  (hidden comment: *)
Capacitor, Ceramic (MLCC), 100uF, ±20%, 10V, X5R, ±20%, SMD 1206; Manufacturer: Murata Electronics; Manufacturer Part Number: GRM31CR61A107ME05L
footprint CAP-1206 (1206 (3216M) Capacitor)
pins: 1, 2

## GRM31CR61A107MEA8L
designator C?  Capacitance: 100uF  (hidden comment: *)
Capacitor, Ceramic (MLCC), 100uF, ±20%, ±20%, SMD 1206; Manufacturer: Murata Electronics; Manufacturer Part Number: GRM31CR61A107MEA8L
footprint CAP-1206 (1206 (3216M) Capacitor)
pins: 1, 2

## GRM31CR61A226ME19L
designator C?  Capacitance: 22uF  (hidden comment: *)
Capacitor, Ceramic (MLCC), 22uF, ±20%, 10V, X5R, ±20%, SMD 1206; Manufacturer: Murata Electronics; Manufacturer Part Number: GRM31CR61A226ME19L
footprint CAP-1206 (1206 (3216M) Capacitor)
pins: 1, 2

## GRM31CR61A475KA01L
designator C?  Capacitance: 4.7uF  (hidden comment: *)
Capacitor, Ceramic (MLCC), 4.7uF, ±10%, 10V, X5R, ±10%, SMD 1206; Manufacturer: Murata Electronics; Manufacturer Part Number: GRM31CR61A475KA01L
footprint CAP-1206 (1206 (3216M) Capacitor)
pins: 1, 2

## GRM31CR61A476KE15L
designator C?  Capacitance: 47uF  (hidden comment: *)
Capacitor, Ceramic (MLCC), 47uF, ±10%, 10V, X5R, ±10%, SMD 1206; Manufacturer: Murata Electronics; Manufacturer Part Number: GRM31CR61A476KE15L
footprint CAP-1206 (1206 (3216M) Capacitor)
pins: 1, 2

## GRM31CR61A476ME15L
designator C?  Capacitance: 47uF  (hidden comment: *)
Capacitor, Ceramic (MLCC), 47uF, ±20%, 10V, X5R, ±20%, SMD 1206; Manufacturer: Murata Electronics; Manufacturer Part Number: GRM31CR61A476ME15L
footprint CAP-1206 (1206 (3216M) Capacitor)
pins: 1, 2

## GRM31CR61C475KA01L
designator C?  Capacitance: 4.7uF  (hidden comment: *)
Capacitor, Ceramic (MLCC), 4.7uF, ±10%, 16V, X5R, ±10%, SMD 1206; Manufacturer: Murata Electronics; Manufacturer Part Number: GRM31CR61C475KA01L
footprint CAP-1206 (1206 (3216M) Capacitor)
pins: 1, 2

## GRM31CR61C476ME44L
designator C?  Capacitance: 47uF  (hidden comment: *)
Capacitor, Ceramic (MLCC), 47uF, ±20%, 16V, X5R, ±20%, SMD 1206; Manufacturer: Murata Electronics; Manufacturer Part Number: GRM31CR61C476ME44L
footprint CAP-1206 (1206 (3216M) Capacitor)
pins: 1, 2

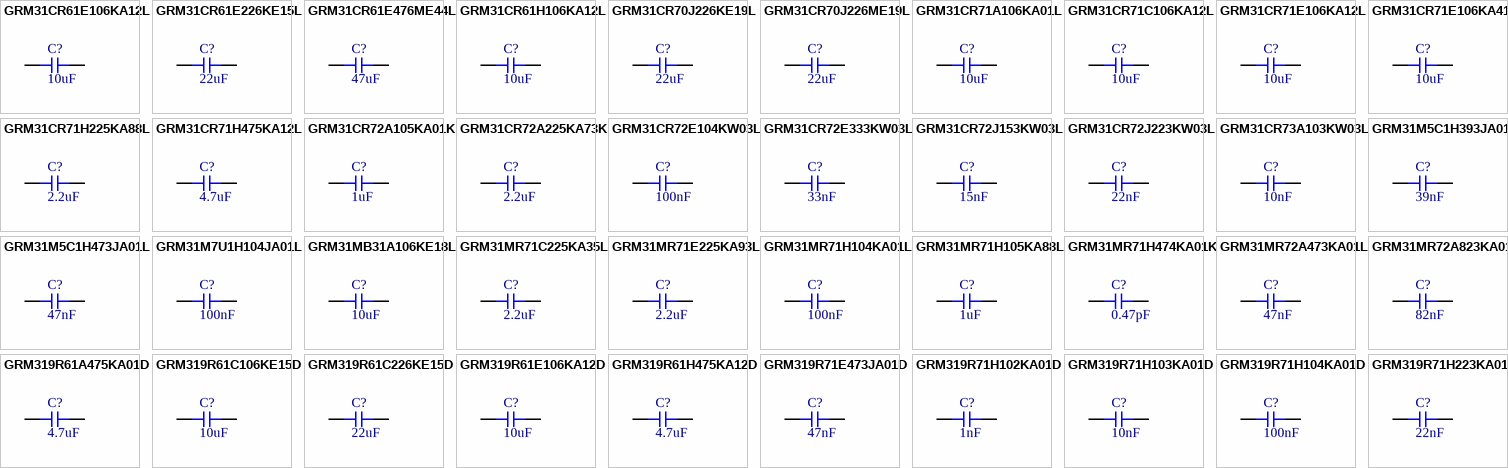
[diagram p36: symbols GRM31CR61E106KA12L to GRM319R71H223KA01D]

## GRM31CR61E106KA12L
designator C?  Capacitance: 10uF  (hidden comment: *)
Capacitor, Ceramic (MLCC), 10uF, ±10%, 25V, X5R, ±10%, SMD 1206; Manufacturer: Murata Electronics; Manufacturer Part Number: GRM31CR61E106KA12L
footprint CAP-1206 (1206 (3216M) Capacitor)
pins: 1, 2

## GRM31CR61E226KE15L
designator C?  Capacitance: 22uF  (hidden comment: *)
Capacitor, Ceramic (MLCC), 22uF, ±10%, 25V, X5R, ±10%, SMD 1206; Manufacturer: Murata Electronics; Manufacturer Part Number: GRM31CR61E226KE15L
footprint CAP-1206 (1206 (3216M) Capacitor)
pins: 1, 2

## GRM31CR61E476ME44L
designator C?  Capacitance: 47uF  (hidden comment: *)
Capacitor, Ceramic (MLCC), 47uF, ±20%, 25V, X5R, ±20%, SMD 1206; Manufacturer: Murata Electronics; Manufacturer Part Number: GRM31CR61E476ME44L
footprint CAP-1206 (1206 (3216M) Capacitor)
pins: 1, 2

## GRM31CR61H106KA12L
designator C?  Capacitance: 10uF  (hidden comment: *)
Capacitor, Ceramic (MLCC), 10uF, ±10%, 50V, X5R, ±10%, SMD 1206; Manufacturer: Murata Electronics; Manufacturer Part Number: GRM31CR61H106KA12L
footprint CAP-1206 (1206 (3216M) Capacitor)
pins: 1, 2

## GRM31CR70J226KE19L
designator C?  Capacitance: 22uF  (hidden comment: *)
Capacitor, Ceramic (MLCC), 22uF, ±10%, 6.3V, X7R, ±10%, SMD 1206; Manufacturer: Murata Electronics; Manufacturer Part Number: GRM31CR70J226KE19L
footprint CAP-1206 (1206 (3216M) Capacitor)
pins: 1, 2

## GRM31CR70J226ME19L
designator C?  Capacitance: 22uF  (hidden comment: *)
Capacitor, Ceramic (MLCC), 22uF, ±20%, ±20%, SMD 1206; Manufacturer: Murata Electronics; Manufacturer Part Number: GRM31CR70J226ME19L
footprint CAP-1206 (1206 (3216M) Capacitor)
pins: 1, 2

## GRM31CR71A106KA01L
designator C?  Capacitance: 10uF  (hidden comment: *)
Capacitor, Ceramic (MLCC), 10uF, ±10%, 10V, X7R, ±10%, SMD 1206; Manufacturer: Murata Electronics; Manufacturer Part Number: GRM31CR71A106KA01L
footprint CAP-1206 (1206 (3216M) Capacitor)
pins: 1, 2

## GRM31CR71C106KA12L
designator C?  Capacitance: 10uF  (hidden comment: *)
Capacitor, Ceramic (MLCC), 10uF, ±10%, 16V, X7R, ±10%, SMD 1206; Manufacturer: Murata Electronics; Manufacturer Part Number: GRM31CR71C106KA12L
footprint CAP-1206 (1206 (3216M) Capacitor)
pins: 1, 2

## GRM31CR71E106KA12L
designator C?  Capacitance: 10uF  (hidden comment: *)
Capacitor, Ceramic (MLCC), 10uF, ±10%, 25V, X7R, ±10%, SMD 1206; Manufacturer: Murata Electronics; Manufacturer Part Number: GRM31CR71E106KA12L
footprint CAP-1206 (1206 (3216M) Capacitor)
pins: 1, 2

## GRM31CR71E106KA41L
designator C?  Capacitance: 10uF  (hidden comment: *)
Capacitor, Ceramic (MLCC), 10uF, ±10%, 25V, X7R, ±10%, SMD 1206; Manufacturer: Murata Electronics; Manufacturer Part Number: GRM31CR71E106KA41L
footprint CAP-1206 (1206 (3216M) Capacitor)
pins: 1, 2

## GRM31CR71H225KA88L
designator C?  Capacitance: 2.2uF  (hidden comment: *)
Capacitor, Ceramic (MLCC), 2.2uF, ±10%, 50V, X7R, ±10%, SMD 1206; Manufacturer: Murata Electronics; Manufacturer Part Number: GRM31CR71H225KA88L
footprint CAP-1206 (1206 (3216M) Capacitor)
pins: 1, 2

## GRM31CR71H475KA12L
designator C?  Capacitance: 4.7uF  (hidden comment: *)
Capacitor, Ceramic (MLCC), 4.7uF, ±10%, 50V, X7R, ±10%, SMD 1206; Manufacturer: Murata Electronics; Manufacturer Part Number: GRM31CR71H475KA12L
footprint CAP-1206 (1206 (3216M) Capacitor)
pins: 1, 2

## GRM31CR72A105KA01K
designator C?  Capacitance: 1uF  (hidden comment: *)
Capacitor, Ceramic (MLCC), 1uF, ±10%, ±10%, SMD 1206; Manufacturer: Murata Electronics; Manufacturer Part Number: GRM31CR72A105KA01K
footprint CAP-1206 (1206 (3216M) Capacitor)
pins: 1, 2

## GRM31CR72A225KA73K
designator C?  Capacitance: 2.2uF  (hidden comment: *)
Capacitor, Ceramic (MLCC), 2.2uF, ±10%, ±10%, SMD 1206; Manufacturer: Murata Electronics; Manufacturer Part Number: GRM31CR72A225KA73K
footprint CAP-1206 (1206 (3216M) Capacitor)
pins: 1, 2

## GRM31CR72E104KW03L
designator C?  Capacitance: 100nF  (hidden comment: *)
Capacitor, Ceramic (MLCC), 100nF, ±10%, 250V, X7R, ±10%, SMD 1206; Manufacturer: Murata Electronics; Manufacturer Part Number: GRM31CR72E104KW03L
footprint CAP-1206 (1206 (3216M) Capacitor)
pins: 1, 2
